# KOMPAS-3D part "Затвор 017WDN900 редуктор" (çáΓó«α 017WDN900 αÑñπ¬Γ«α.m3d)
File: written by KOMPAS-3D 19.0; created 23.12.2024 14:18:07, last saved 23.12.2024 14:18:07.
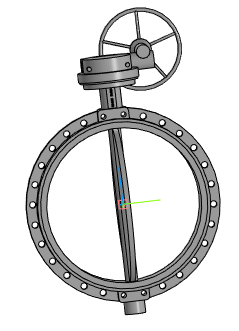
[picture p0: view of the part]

Document properties: Автор: Евгений; Полное имя файла: ..\Затвор 017WDN900 редуктор.a3d

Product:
- Part/product: Затвор 017WDN900 редуктор
    Масса: 630.886

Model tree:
1. Операция без истории:1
